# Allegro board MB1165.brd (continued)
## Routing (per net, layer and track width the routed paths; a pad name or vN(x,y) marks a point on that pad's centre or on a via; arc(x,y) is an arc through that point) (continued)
PWR_ENN: length 13.8
  TOP w0.127: U21.28 39.22,45.59 R147.2
  TOP w0.254: U18.3 R147.2
RESET#: length 385.7
  TOP w0.127: CN18.36 72.07,39.43 73.41,38.1 73.41,35.38 68.39,30.37 68.39,27.24 62.61,21.46 55.05,21.46 52.83,23.69 v1(52.83,24.13) 52.83,24.66 D16.2 ; U4.J1 77.54,142.96 77.54,144.21 v5(77.5,144.25) ; v1(133.88,120.47) 133.53,120.47 132.96,121.04 U6.29 ; R96.2 126.62,106.81 127.56,106.81 v1(128.27,107.51) ; B1.2 B1.3 53.78,10.99 C102.2 v1(53.72,12.19) ; U21.18 39.52,33.41 39.11,32.99 v1(37.97,32.99) ; v1(28.05,138.03) v1(33.43,138.03) D2.1 ; R114.2 20.71,100.2 21.59,99.33 21.59,98.81 v1(22.61,97.79)
  L3_SIG w0.102: v1(120.52,152.78) 119.68,153.62 111.28,153.62 110.97,153.92 91.59,153.92 87.91,150.24 83.69,150.24 82.04,148.59 82.04,147.57 80.39,145.92 80.39,144.91 79.45,143.97 77.78,143.97 v5(77.5,144.25) 77.39,144.35 77.39,146.41 76.09,147.71 73.65,147.71 69.52,151.84 66.6,151.84 64.54,153.9 43.79,153.9 43.43,153.54 v1(43.28,153.54) 43.15,153.42 40.64,153.42 39.93,152.7 38.28,152.7 33.22,147.65 33.22,142.95 33.58,142.6 33.58,138.18 v1(33.43,138.03) ; v1(23.14,113.26) 22.05,114.35 22.05,118.06 28.05,124.06 v1(28.05,138.03) ; v1(52.83,24.13) 52.83,26.44 51.33,27.94 44.96,27.94 39.9,32.99 v1(37.97,32.99) 37.49,32.99 33.4,37.08 33.4,43.69 31.5,45.59 31.5,61.85 30.86,62.48 30.86,69.11 28.07,71.91 28.07,86.11 27.33,86.84 27.33,93.07 v1(22.61,97.79)
  BOTTOM w0.127: v1(53.72,12.19) 51.18,14.73 51.18,22.48 v1(52.83,24.13) ; v1(22.61,97.79) 22.02,98.37 22.02,112.14 v1(23.14,113.26) ; R213.1 42.8,154.31 42.8,154.05 43.28,153.57 v1(43.28,153.54) ; v1(120.52,152.78) 128.65,144.65 128.65,129.39 132.36,125.68 132.36,121.77 133.65,120.47 v1(133.88,120.47) 132.74,119.33 132.74,110.36 129.89,107.51 v1(128.27,107.51)
STL_USB_DM: length 35.9
  TOP w0.155: R177.2 17.72,23.56 18.73,23.56 20.7,25.53 20.7,28.86 26.54,34.7 26.54,40.54 27.66,41.66 35.56,41.66 37.16,40.05 37.16,38.99 37.22,38.93 U21.32
STL_USB_DP: length 35.2
  TOP w0.155: R180.2 17.72,23.18 18.89,23.18 21.08,25.37 21.08,28.7 26.92,34.54 26.92,40.39 27.81,41.27 35.4,41.27 36.78,39.89 36.78,38.99 36.72,38.93 U21.33
STLINK_RX: length 47
  TOP w0.127: CN24.1 51.18,17.53 51.18,22.61 42.88,30.9 U21.13
  BOTTOM w0.127: CN24.1 49.02,13.34 51.44,10.92 56.01,10.92 67.06,21.97 JP19.3
STLINK_TX: length 48.9
  TOP w0.127: CN24.2 49.02,23.75 43.47,29.3 U21.12
  BOTTOM w0.127: CN24.2 50.16,16.76 50.16,13.34 52.07,11.43 55.5,11.43 65.66,21.59 65.66,26.54 JP15.3
STM_JTCK_SWCLK: length 6.3
  TOP w0.127: CN20.3 29.34,35.43 31.5,35.43 32.47,36.41 U21.37
STM_JTMS_SWDIO: length 9.9
  TOP w0.127: CN20.1 29.34,37.97 33.53,37.97 34.67,36.83 35.81,36.83 36.22,37.24 U21.34
STM_RST: length 6.4
  TOP w0.127: v1(39.12,31.62) 38.22,30.73 U21.7
  BOTTOM w0.127: R291.1 SB84.2 C181.2 v1(39.12,31.62)
T_JTDO: length 258.4
  TOP w0.127: R92.2 127.13,108.58 v1(127.38,108.33) ; v1(133.35,141.35) 133.35,138.3 136.14,135.51 145.29,135.51 146.43,134.37 146.43,130.43 148.08,128.78 150.14,128.78 151.26,127.67 151.26,126.24 151.69,125.81 v1(151.69,125.78) ; U21.16 41,32.41 40.87,32.54 37.69,32.54 36.96,33.27 36.96,35.18 v1(37.72,35.94) U21.31
  L3_SIG w0.102: JP5.1 99.52,132.41 112.85,132.41 113.39,131.88 119.68,131.88 127.89,140.08 132.08,140.08 v1(133.35,141.35) ; v1(151.69,125.78) 151.69,120.86 150.21,119.38 145.89,119.38 142.34,115.82 140.69,115.82 137,112.14 133.48,112.14 130.81,109.47 127.89,109.47 127.38,108.97 v1(127.38,108.33) 127.38,106.17 128.5,105.05 128.5,101.5 126.85,99.85 125.35,99.85 123.04,97.54 121.74,97.54 118.73,94.53 118.73,93.43 112.52,87.22 112.52,81.03 112.9,80.64 112.9,77.52 110.24,74.85 110.24,72.85 78.54,41.15 62.92,41.15 61.26,39.5 57.02,39.5 56.44,40.08 52.22,40.08 50.29,38.15 50.29,34.29 47.9,31.9 44.53,31.9 44.07,32.36 44.07,32.51 43.69,32.89 42.8,32.89 40.51,35.18 38.49,35.18 v1(37.72,35.94)
TOUCH_INT: length 92.9
  TOP w0.127: v1(58.01,40.39) U22.27 ; CN15.4 110.32,80.65 109.93,80.26 108.28,80.26 105.66,77.65 105.66,55.12 104.14,53.59 70.87,53.59 68.83,51.56 68.83,47.12 69.53,46.42 CN18.39 v1(69.53,42.61)
  L3_SIG w0.102: v1(69.53,42.61) 68.33,43.81 61.44,43.81 v1(58.01,40.39)
U5V_ST_LINK: length 36.3
  TOP w0.508: 35.83,58.04 C59.2 35.18,57.43 ; 36.22,57.53 U18.6 ; U18.7 34.95,57.02
  BOTTOM w1.016: 35.48,60.91 5.38,60.91 4.57,61.72 JP14.11
  vias: v1(36.2,60.07) v1(36.2,59.44)
ULPI_D1: length 76.3
  TOP w0.127: U8.23 31.73,107.29 33.78,109.35 36.5,109.35 37.13,108.71 v1(37.13,107.19)
  L3_SIG w0.102: v1(44.96,124.33) 47.75,124.33 47.88,124.21 47.88,123.83 47.75,123.7 42.8,123.7 42.67,123.57 42.67,123.32 42.8,123.19 44.2,123.19 44.32,123.06 44.32,122.81 44.2,122.68 42.8,122.68 42.67,122.56 42.67,122.35 42.8,122.22 43.7,122.22 43.81,122.11 43.81,121.94 43.7,121.82 42.77,121.82 42.67,121.72 42.67,121.51 42.77,121.41 43.59,121.41 43.69,121.31 43.69,121.11 43.59,121.01 42.77,121.01 42.67,120.9 42.67,116.46 42.55,116.33 41.02,116.33 40.89,116.21 40.89,116.03 41.02,115.91 43.18,115.91 43.28,115.81 43.28,115.61 43.18,115.5 41.05,115.5 40.92,115.38 40.92,115.22 41.05,115.1 43.18,115.1 43.28,115 43.28,114.79 43.18,114.69 41.05,114.69 40.92,114.56 40.92,114.41 41.05,114.29 43.18,114.29 43.28,114.18 43.28,113.98 43.18,113.88 41.05,113.88 40.92,113.75 40.92,113.6 41.05,113.47 43.18,113.47 43.28,113.37 43.28,113.17 43.18,113.07 41.05,113.07 40.92,112.94 40.92,112.71 41.02,112.61 42.82,112.61 42.93,112.51 42.93,112.09 42.66,111.82 42.51,111.82 42.1,112.24 41.95,112.24 41.81,112.09 41.81,111.95 42.23,111.53 42.23,111.39 42.08,111.25 41.94,111.25 41.52,111.66 41.38,111.66 41.24,111.52 41.24,111.37 41.65,110.96 41.65,110.81 41.51,110.67 41.36,110.67 40.95,111.09 40.8,111.09 40.66,110.94 40.66,110.8 41.08,110.38 41.08,110.24 40.93,110.1 40.79,110.1 40.37,110.51 40.23,110.51 40.09,110.37 40.09,110.22 40.5,109.81 40.5,109.66 40.36,109.52 40.21,109.52 39.8,109.94 39.65,109.94 39.51,109.79 39.51,109.65 39.92,109.23 39.92,109.09 39.78,108.95 39.64,108.95 39.22,109.36 39.08,109.36 38.93,109.22 38.93,109.07 39.35,108.66 39.35,108.51 39.21,108.37 39.06,108.37 38.65,108.79 38.5,108.79 38.36,108.64 38.36,108.5 38.77,108.08 38.77,107.94 38.63,107.8 38.49,107.8 38.07,108.21 37.93,108.21 37.78,108.07 37.78,107.48 37.49,107.19 v1(37.13,107.19)
  BOTTOM w0.127: SB79.1 v1(44.96,124.33)
ULPI_D2: length 85.3
  TOP w0.127: U8.22 31.99,106.8 33.91,108.71 v1(34.8,108.71)
  L3_SIG w0.102: v1(44.83,140.72) 47.98,140.72 48.11,140.84 48.11,141.07 47.98,141.2 38.63,141.2 38.51,141.07 38.51,140.84 38.63,140.72 42.67,140.72 42.8,140.59 42.8,140.41 42.67,140.29 38.65,140.29 38.53,140.17 38.53,140 38.65,139.88 42.68,139.88 42.8,139.76 42.8,139.59 42.68,139.47 38.63,139.47 38.51,139.35 38.51,139.19 38.63,139.07 42.91,139.07 43.03,138.95 43.03,138.78 42.91,138.66 38.63,138.66 38.51,138.53 38.51,132.36 37.97,131.83 37.97,125.5 38.51,124.97 38.51,115.15 38.4,115.04 37.67,115.04 37.57,114.94 37.57,114.74 37.67,114.64 38.4,114.64 38.51,114.54 38.51,114.33 38.4,114.23 37.36,114.23 37.24,114.11 37.24,113.94 37.36,113.82 38.4,113.82 38.51,113.72 38.51,113.52 38.4,113.42 37.38,113.42 37.26,113.3 37.26,113.13 37.38,113.01 38.4,113.01 38.51,112.91 38.51,112.42 v1(34.8,108.71)
  BOTTOM w0.127: SB50.1 45.34,141.22 v1(44.83,140.72)
ULPI_D5: length 70.6
  TOP w0.127: U8.19 32.5,105.29 33.27,104.52 v1(34.8,104.52)
  L3_SIG w0.102: v1(34.8,104.52) 35.66,104.52 35.79,104.65 35.79,107.47 39.98,111.66 39.98,117.31 40.18,117.51 41.28,117.51 41.4,117.63 41.4,117.8 41.28,117.92 40.03,117.92 39.93,118.02 39.93,118.22 40.03,118.32 41.55,118.32 41.66,118.42 41.66,118.63 41.55,118.73 40.03,118.73 39.93,118.83 39.93,119.03 40.03,119.14 41.55,119.14 41.66,119.24 41.66,119.44 41.55,119.54 40.03,119.54 39.93,119.64 39.93,119.85 40.03,119.95 41.55,119.95 41.66,120.05 41.66,120.25 41.55,120.36 40.03,120.36 39.93,120.46 39.93,120.66 40.03,120.76 41.55,120.76 41.66,120.86 41.66,121.07 41.55,121.17 40.03,121.17 39.93,121.27 39.93,121.47 40.03,121.57 41.55,121.57 41.66,121.68 41.66,121.88 41.55,121.98 40.03,121.98 39.93,122.08 39.93,122.29 40.03,122.39 41.55,122.39 41.66,122.49 41.66,122.69 41.55,122.79 40.03,122.79 39.93,122.9 39.93,123.1 40.03,123.2 41.55,123.2 41.66,123.3 41.66,123.5 41.55,123.61 40.03,123.61 39.93,123.71 39.93,123.91 40.03,124.01 41.55,124.01 41.66,124.11 41.66,124.32 41.55,124.42 40.03,124.42 39.93,124.52 39.93,124.72 40.03,124.83 41.55,124.83 41.66,124.93 41.66,125.13 41.55,125.23 40.03,125.23 39.93,125.33 39.93,125.7 40.06,125.83 42.19,125.83 42.32,125.96 42.32,126.24 42.19,126.36 40.06,126.36 39.93,126.49 39.93,126.72 40.06,126.85 40.69,126.85 40.82,126.97 40.82,128.64 40.69,128.76 39.84,128.76 v1(39.52,128.45)
  BOTTOM w0.127: SB74.1 39.85,128.91 39.52,128.57 v1(39.52,128.45)
ULPI_D7: length 61.8
  TOP w0.127: U8.17 v1(31.7,104.29)
  L3_SIG w0.102: v1(43.81,152.58) 41.45,152.58 39.62,150.75 39.24,150.75 35.05,146.56 35.05,145.11 34.42,144.48 34.42,125.6 36.45,123.57 36.45,116.13 35.05,114.73 35.05,113.03 31.7,109.68 v1(31.7,104.29)
  BOTTOM w0.127: SB29.1 46.86,153.16 45.47,153.16 44.88,152.58 v1(43.81,152.58)
USB_RENUMN: length 21.2
  TOP w0.127: U21.38 32.73,35.9 29.59,32.77 27.18,32.77 23.24,28.83 v1(23.24,21.84)
  BOTTOM w0.127: R293.2 v1(23.24,21.84)
VREF+: length 15.5
  TOP w0.381: v5(73.21,143.29) 73.61,142.89 U4.P1
  TOP w0.508: R33.2 v1(67.94,145.54)
  BOTTOM w0.381: v5(73.21,143.29) 73.21,143.31 73.66,143.76 C113.2
  BOTTOM w0.508: v5(73.21,143.29) 72.87,143.29 72.26,143.89 69.72,143.89 68.07,145.54 v1(67.94,145.54) 67.18,146.3 C108.1 66.55,148.72 TP6.1
VUSB_ST_LINK: length 83.8
  TOP w0.508: 34.47,50.59 U18.2 ; U18.2 34.95,49.5 ; U18.2 34.95,51.94 ; 31.75,49.33 C65.1 ; C65.1 32.72,50.16 ; C65.1 30.78,50.16 ; C65.1 31.75,51 ; 31.27,52.45 R144.1 ; R144.1 31.88,51.85 ; R144.1 32.49,52.45 ; R147.1 35.2,49.07 ; R147.1 35.2,48.11 ; R147.1 34.72,48.59 ; D11.1 27.43,76.96 ; D11.1 26.82,77.57 ; D11.1 26.82,76.35 ; D11.1 26.2,76.96 ; CN22.1 11.68,21.59 R187.1 ; 33.2,50.59 U18.1 ; U18.1 33.68,49.5 ; U18.1 34.16,50.59 ; U18.1 33.68,51.68
  L3_SIG w1.016: 18.97,22.43 26.37,29.82 26.37,42.52 28.83,44.98 v1(28.83,52.73) ; 26.29,75.69 26.29,73.28 25.4,72.39 25.4,63.88 28.83,60.45 v1(28.83,56.39)
  BOTTOM w0.508: 19.3,22.33 R292.2 18.71,21.72
  BOTTOM w1.016: 17.02,22.23 CN22.1
  vias: v1(17.98,22.33) v1(18.01,21.62) v1(18.57,22.63) v1(25.91,77.34) v1(25.91,76.58) v1(28.8,55.37) v1(28.8,54.66) v1(28.8,53.9)

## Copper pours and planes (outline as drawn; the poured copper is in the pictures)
+1V8 on TOP: 107.06,43.05 108.46,43.05 108.97,43.56 108.97,47.62 109.22,47.88 110.49,47.88 110.87,47.5 110.87,43.56 111.38,43.05 119.51,43.05 120.14,42.42 120.14,38.35 119.63,37.85 107.06,37.85 106.68,38.23 106.68,42.67
+1V8 on BOTTOM: 154.56,159.38 154.81,159.13 154.81,156.72 154.56,156.46 148.13,156.46 147.45,155.78 147.45,119.25 139.01,110.82 139.01,100.3 138.53,99.82 136.4,99.82 136.02,100.2 136.02,111.46 143.89,119.33 143.89,153.85 143.76,153.97 143.76,158.37 144.78,159.38
+1V8 on BOTTOM: 121.34,42.67 121.36,42.7 121.72,42.7 122.1,42.32 122.1,24.99 121.69,24.59 118.26,24.59 117.84,25.01 117.84,27.01 118.29,27.46 118.29,28.75 114.94,32.11 114.94,42.34 115.27,42.67
+1V8 on L3_SIG: 134.75,101.47 137.79,101.47 138.3,100.97 138.3,98.42 123.06,83.19 123.06,40.89 120.14,37.97 116.08,37.97 115.82,38.23 115.82,42.67 116.71,43.56 117.98,43.56 119.25,44.83 119.25,88.39 123.38,92.52 125.79,92.52
+2V8 on TOP: 140.08,156.59 140.46,156.21 140.46,151 140.21,150.75 131.06,150.75 130.43,151.38 130.43,155.32 131.83,156.72 131.83,160.53 131.95,160.66 133.6,160.66 133.73,160.53 133.73,157.23 134.37,156.59
+2V8 on L4_VCC: 136.76,137.16 134.87,139.04 134.87,156.1 137.27,158.5 156.34,158.5 156.34,148.34 156.34,148.33 156.34,146.18 156.21,146.05 153.03,146.05 152.15,145.16 152.15,137.77 151.53,137.16
+3V3 on TOP: 106.3,48.51 108.2,48.51 108.46,48.26 108.46,44.7 108.2,44.45 106.3,44.45 106.05,44.7 106.05,48.26
+3V3 on TOP: 43.31,56.13 60.33,56.13 60.71,55.75 60.71,52.32 60.2,51.82 56.26,51.82 55.75,51.31 55.75,44.2 55.24,43.69 43.56,43.69 42.55,44.7 42.55,55.37
+3V3 on L4_VCC: 0.51,0.51 0.51,13.93 19.56,13.93 20.19,14.57 20.19,15.62 20.45,15.88 30.32,15.88 31.33,16.89 31.33,26.01 31.97,26.65 40.54,26.65 42.5,28.61 42.5,40.06 41.02,41.54 26.76,41.54 24.07,44.24 24.07,69.76 22.46,71.36 0.51,71.36 0.51,82.03 2,82.03 2.39,82.43 2.39,83.5 2,83.9 0.51,83.9 0.51,86.78 2,86.78 2.39,87.18 2.39,88.25 2,88.65 0.51,88.65 0.51,96.39 2,96.39 2.39,96.78 2.39,97.86 2,98.25 0.51,98.25 0.51,101.14 2,101.14 2.39,101.53 2.39,102.61 2,103 0.51,103 0.51,106.93 5.95,106.93 6.6,107.59 6.6,111.1 5.95,111.76 3.41,111.76 3.3,111.87 3.3,113.69 3.41,113.79 5.19,113.79 6.35,114.96 6.35,116.1 6.96,116.71 7.34,116.71 8,117.37 8,118.85 7.6,119.25 0.51,119.25 0.51,172.21 156.34,172.21 156.34,159 137.05,159 134.37,156.32 134.37,138.83 136.55,136.65 151.74,136.65 152.65,137.56 152.65,144.91 153.29,145.54 155.96,145.54 156.34,145.16 156.34,52.91 155.69,47.08 156.34,41.24 156.34,0.51 ; 1 cut-out
+3V3_ST_LINK on L4_VCC: 0.51,14.44 0.51,70.86 22.25,70.86 23.56,69.55 23.56,44.03 26.55,41.03 40.81,41.03 42,39.85 42,28.82 40.33,27.16 31.76,27.16 30.83,26.22 30.83,17.27 30.06,16.51 20.19,16.51 19.56,15.88 19.56,14.82 19.18,14.44
+5V on TOP: 130.68,157.48 128.78,157.48 128.27,157.99 128.27,162.23 128.47,162.43 130.86,162.43 131.06,162.23 131.06,157.86
+5V on TOP: 6.02,76.35 6.54,76.87 13.32,76.87 13.77,76.43 13.77,71.04 13.83,70.98 13.83,68.47 15.75,66.55 44.89,66.55 46.61,68.26 48.2,68.26 48.64,67.82 48.64,62.61 47.88,61.85 47.88,56.9 47.62,56.64 43.81,56.64 43.43,57.02 43.43,59.69 41.91,61.21 6.65,61.21 6.02,61.85
+5V on BOTTOM: 13.84,92.15 12.09,92.15 11.68,92.56 11.68,97.97 16.59,102.87 16.59,115.16 17.22,115.8 21.01,115.8 21.21,115.6 21.21,114.17 19.91,112.88 19.91,102.57 14.05,96.7 14.05,92.35
+5V on L3_SIG: 8.66,97.46 13.21,97.46 13.74,96.93 13.74,72.75 12.62,71.63 6.38,71.63 6.05,71.96 6.05,76.63 10.64,81.23 10.64,94.36 10.19,94.82 8.81,94.82 8.51,95.12 8.51,97.31
+5V on L3_SIG: 130.07,161.59 128.57,161.59 128.32,161.85 128.32,167.94 125.93,170.33 115.44,170.33 110.39,165.28 109.65,165.28 107.92,167 71.27,167 69.9,168.38 30.23,168.38 28.92,167.07 28.92,156.53 28.57,156.18 28.57,149.61 19.3,140.34 19.3,118.24 20.93,116.61 20.95,116.61 21.36,116.2 21.36,113.51 21.03,113.18 17.5,113.18 12.19,118.49 12.19,142.56 25.34,155.7 25.34,168.16 28.42,171.25 113.42,171.25 114.16,171.98 127.91,171.98 130.33,169.57 130.33,161.85
D5V on TOP: 42.93,125.91 44.22,125.91 44.58,125.55 44.58,121.62 45.06,121.13 45.06,120.7 44.88,120.52 43.97,120.52 43.64,120.85 43.64,122.58 43.66,122.61 43.66,124.69 43.31,125.04 43.03,125.04 42.93,125.15
D5V on TOP: 39.67,125.68 39.67,123.88 37.21,121.41 26.59,121.41 26.42,121.59 26.42,122.56 26.67,122.81 36.07,122.81 39.12,125.86 39.5,125.86
D5V on TOP: 106.93,125.98 108.28,125.98 108.38,125.88 108.38,124.97 108.25,124.84 106.93,124.84 106.81,124.97 106.81,125.86
D5V on BOTTOM: 14.68,95.22 15.21,95.22 21.54,101.55 21.54,112.12 22.89,113.46 22.89,116.71 27.61,121.44 28.07,121.44 28.27,121.64 28.27,122.66 28.09,122.83 26.82,122.83 21.84,117.86 21.84,113.92 20.42,112.5 20.42,102.06 14.43,96.06 14.43,95.48
D5V on L3_SIG: 107.19,125.98 108.33,125.98 108.58,125.73 108.58,124.59 105.92,121.92 98.73,121.92 96.57,119.76 62.36,119.76 60.55,121.56 47.88,121.56 46.58,120.27 44.07,120.27 43.94,120.4 43.94,121.54 44.2,121.79 45.82,121.79 46.58,122.56 61.21,122.56 62.74,121.03 96.06,121.03 98.09,123.06 104.9,123.06 106.81,124.97 106.81,125.6
D5V on L3_SIG: 14.71,96.47 15.6,96.47 15.75,96.32 15.75,77.22 15.49,76.96 15.49,73.91 15.75,73.66 15.75,71.93 10.36,66.55 3.84,66.55 3.4,66.98 3.4,68.99 3.73,69.32 8.36,69.32 8.56,69.11 10.97,69.11 14.22,72.36 14.22,95.99
GND on BOTTOM (solid shape): 37.59,29.56 38.1,30.06 38.1,28.7 37.08,28.7 37.08,30.07
GND on TOP: 111.89,48.51 118.75,48.51 119,48.26 119,44.32 118.62,43.94 111.89,43.94 111.63,44.2 111.63,48.26
GND on TOP: 22.23,60.33 27,60.33 27.46,59.87 27.46,55.24 26.82,54.61 22.1,54.61 21.72,54.99 21.72,59.82
GND on TOP: 141.48,156.34 143.64,156.34 144.15,155.83 144.15,151.38 143.64,150.88 141.22,150.88 140.97,151.13 140.97,155.83
GND on TOP: 54.48,56.9 54.23,56.64 50.55,56.64 50.36,56.83 50.36,61.28 50.16,61.47 50.16,66.59 51.14,67.56 59.5,67.56 61.59,65.47 61.59,57.15 61.34,56.9
GND on TOP: 77.6,151.38 69.47,151.38 69.22,151.64 69.22,155.45 71.75,157.99 91.57,157.99 91.95,157.61 91.95,150.75 91.03,149.83 87.02,149.83 85.72,151.13 77.85,151.13
GND on TOP: 27.69,19.05 26.67,20.07 26.67,31.37 27.56,32.26 30.21,32.26 30.34,32.13 30.34,30.75 32.4,28.68 32.4,26.82 33.13,26.09 43.94,26.09 45.21,24.82 45.21,20.4 43.87,19.05
GND on TOP: 22.86,117.86 34.67,117.86 34.92,117.6 34.92,113.41 32.89,111.38 30.48,111.38 30.48,112.78 26.8,112.78 26.8,111.38 25.53,111.38 25.34,111.19 25.34,109.41 25.15,109.22 22.35,109.22 21.97,109.6 21.97,116.97
GND on TOP: 144.17,132.08 144.53,131.72 144.53,117.35 144.27,117.09 137.79,117.09 137.29,117.6 137.29,131.32 138.05,132.08
GND on BOTTOM: 70.82,156.64 80.01,156.64 80.7,155.96 80.7,152.4 79.55,151.26 71.04,151.26 69.14,153.16 69.14,154.97
GND on BOTTOM: 31.47,25.98 44.15,25.98 45.11,25.02 45.11,19.86 44.48,19.23 31.24,19.23 30.78,19.68 30.78,25.3
GND on BOTTOM: 24.92,117.91 32.44,117.91 33.63,116.71 33.63,112.55 32.64,111.56 24.43,111.56 24.42,111.57 24.23,111.57 23.94,111.86 22.66,111.86 22.56,111.96 22.56,112.34 23.22,113 23.22,116.2
GND on L2_GND, L5_GND: 0.51,0.51 0.51,82.03 2,82.03 2.39,82.43 2.39,83.5 2,83.9 0.51,83.9 0.51,86.78 2,86.78 2.39,87.18 2.39,88.25 2,88.65 0.51,88.65 0.51,96.39 2,96.39 2.39,96.78 2.39,97.86 2,98.25 0.51,98.25 0.51,101.14 2,101.14 2.39,101.53 2.39,102.61 2,103 0.51,103 0.51,106.93 5.95,106.93 6.6,107.59 6.6,111.1 5.95,111.76 3.41,111.76 3.3,111.87 3.3,113.69 3.41,113.79 5.19,113.79 6.35,114.96 6.35,116.1 6.96,116.71 7.34,116.71 8,117.37 8,118.85 7.6,119.25 0.51,119.25 0.51,172.21 156.34,172.21 156.34,52.91 155.69,47.08 156.34,41.24 156.34,0.51
GND on L3_SIG: outline of 152 points within 0.56,0.64 156.34,119.63
GND on L3_SIG: 41.15,106.3 48.39,106.3 49.91,104.78 49.91,79.5 66.42,62.99 90.55,62.99 92.84,65.28 93.47,65.28 93.6,65.15 93.6,60.58 81.53,48.51 69.47,48.51 68.2,47.24 59.44,47.24 58.93,46.74 58.93,45.34 54.99,41.4 51.69,41.4 48.11,37.82 35.81,37.82 35.18,38.46 35.18,45.47 34.54,46.1 34.54,61.59 33.02,63.12 33.02,70.36 29.84,73.53 29.84,93.55 39.5,103.2 39.5,104.65
GND on L3_SIG: 24.23,118.49 33.22,118.49 33.99,117.73 33.99,113.11 30.81,109.93 30.81,103.58 30.1,102.87 24.21,102.87 23.75,103.33 23.75,106.81 22.1,108.46 22.1,112.09 22.83,112.83 22.83,117.09
VBUS_FS2 on TOP (solid shape): 15.24,113.54 14.22,113.54 14.22,114.9 14.73,114.39 15.24,114.9
VDD_MCU on BOTTOM: 59.56,149.86 60.58,150.88 61.85,150.88 62.36,150.37 62.36,139.06 62.1,138.81 59.82,138.81 59.56,139.06
VDD_MCU on L4_VCC: 58.78,130.3 58.17,130.92 58.17,150.52 58.78,151.13 61.87,151.13 62.23,150.77 62.23,148.23 62.89,147.57 71.73,147.57 74.27,150.11 87.78,150.11 89.41,148.48 89.41,131.93 87.78,130.3
DSI_VDD12 on BOTTOM: 77.7,132.77 78.03,132.44 78.03,132.23 77.98,132.18 77.17,132.18 76.34,133.01 76.34,134.79 76.48,134.92 77.6,134.92 77.7,134.82
E5V on TOP: 20.83,55.12 20.83,59.82 20.32,60.33 6.1,60.33 5.72,60.71 5.72,65.79 5.21,66.29 1.27,66.29 1.02,66.04 1.02,54.74 1.4,54.36 10.92,54.36 11.3,54.74 20.45,54.74
LCD_BL_CTRL on BOTTOM (solid shape): 116.59,123.44 115.22,123.44 115.73,123.95 115.22,124.46 116.59,124.46
LCD_G0 on BOTTOM (solid shape): 46.45,139.7 46.95,139.19 45.59,139.19 45.59,140.21 46.96,140.21
LCD_G1 on BOTTOM (solid shape): 46.45,125.85 46.95,125.35 45.59,125.35 45.59,126.36 46.96,126.36
LCD_G5 on BOTTOM (solid shape): 38.39,137.41 37.88,136.91 36.96,136.91 36.96,137.92 37.88,137.92
LCD_G6 on BOTTOM (solid shape): 41.43,153.67 40.93,153.16 40.01,153.16 40.01,154.18 40.93,154.18
LCD_G7 on BOTTOM (solid shape): 48.13,155.19 46.77,155.19 47.28,155.7 46.77,156.21 48.13,156.21
LCD_R0 on TOP (solid shape): 95.5,141.5 94.58,141.5 94.08,142.01 94.58,142.52 95.5,142.52
MIC_CLK on BOTTOM (solid shape): 120.65,15.53 120.14,16.04 119.63,15.53 119.63,16.89 120.65,16.89
MIC_DATA on BOTTOM (solid shape): 129.92,16.1 129.41,15.59 128.91,16.1 128.91,17.02 129.92,17.02
MII_TXD0 on BOTTOM (solid shape): 96.16,155.65 94.8,155.65 95.31,156.16 94.8,156.67 96.16,156.67
NETC5_1 on TOP: 134.49,163.32 136.53,163.32 137.03,162.81 137.03,159.64 137.16,159.51 139.19,159.51 139.45,159.26 139.45,157.35 139.19,157.1 134.87,157.1 134.24,157.73 134.24,163.07
NETC6_2 on TOP (solid shape): 64.64,159.99 64.14,159.48 63.63,159.99 63.63,160.91 64.64,160.91
NETC6_2 on BOTTOM (solid shape): 40.86,144.4 41.37,143.89 40.01,143.89 40.01,144.91 41.37,144.91
NETC7_2 on TOP (solid shape): 70.99,160.12 70.48,159.61 69.98,160.12 69.98,161.04 70.99,161.04
NETC7_2 on BOTTOM (solid shape): 116.59,132.72 115.22,132.72 115.73,133.23 115.22,133.73 116.59,133.73
NETC8_2 on BOTTOM (solid shape): 48.13,150.24 46.77,150.24 47.28,150.75 46.77,151.26 48.13,151.26
NETC9_2 on BOTTOM (solid shape): 40.86,147.52 41.37,147.02 40.01,147.02 40.01,148.03 41.37,148.03
NETC10_2 on BOTTOM (solid shape): 109.57,130.81 110.07,130.3 108.71,130.3 108.71,131.32 110.08,131.32
NETC11_1 on BOTTOM (solid shape): 48.13,130.05 47.21,130.05 46.7,130.56 47.21,131.06 48.13,131.06
NETC12_2 on BOTTOM (solid shape): 48.13,136.14 47.21,136.14 46.7,136.65 47.21,137.16 48.13,137.16
NETC13_2 on BOTTOM (solid shape): 42.67,140.84 41.75,140.84 41.24,141.35 41.75,141.86 42.67,141.86
NETC14_2 on BOTTOM (solid shape): 48.13,147.07 47.21,147.07 46.7,147.57 47.21,148.08 48.13,148.08
NETC15_1 on BOTTOM (solid shape): 41.56,139.06 41.05,138.56 40.13,138.56 40.13,139.57 41.05,139.57
NETC17_1 on TOP (solid shape): 64.64,158.37 63.63,158.37 63.63,159.73 64.13,159.22 64.64,159.73
NETC18_2 on TOP (solid shape): 70.99,158.5 69.98,158.5 69.98,159.86 70.48,159.35 70.99,159.86
NETC18_2 on BOTTOM (solid shape): 116.59,126.49 115.22,126.49 115.73,127 115.22,127.51 116.59,127.51
NETC35_1 on TOP: 0.89,107.57 0.51,107.95 0.51,109.6 0.64,109.73 2.03,109.73 2.41,110.11 2.41,111.51 2.16,111.76 0.76,111.76 0.53,111.99 0.53,114.5 0.58,114.55 0.64,114.55 0.68,114.6 2,114.6 2.39,115 2.39,116.07 2,116.47 0.76,116.47 0.64,116.59 0.64,118.75 5.72,118.75 5.84,118.87 7.24,118.87 7.49,118.62 7.49,117.6 7.11,117.22 6.73,117.22 5.84,116.33 5.84,114.94 5.08,114.17 3.3,114.17 3.05,113.92 3.05,111.76 3.43,111.38 5.59,111.38 6.22,110.74 6.22,107.82 5.97,107.57
NETC35_1 on L2_GND, L4_VCC, L5_GND: 0.51,107.44 0.51,109.85 2,109.85 2.39,110.25 2.39,111.32 2,111.72 0.51,111.72 0.51,114.6 2,114.6 2.39,115 2.39,116.07 2,116.47 0.51,116.47 0.51,118.75 7.39,118.75 7.49,118.64 7.49,117.58 7.13,117.22 6.75,117.22 5.84,116.31 5.84,115.17 4.97,114.3 3.2,114.3 2.79,113.9 2.79,111.65 3.2,111.25 5.74,111.25 6.1,110.89 6.1,107.8 5.74,107.44
NETC37_1 on TOP (solid shape): 15.24,115.16 14.73,114.65 14.22,115.16 14.22,116.08 15.24,116.08
NETC37_1 on TOP (solid shape): 11.94,114.72 11.43,115.22 10.92,114.71 10.92,116.08 11.94,116.08
NETC63_1 on TOP: 65.15,52.76 66.93,52.76 67.06,52.63 67.06,47.42 66.17,46.53 65.41,46.53 64.9,47.04 64.9,52.5
NETC63_2 on TOP: 61.98,52.76 63.88,52.76 64.26,52.38 64.26,46.92 64.68,46.5 64.68,46.11 64.77,46.03 64.77,43.36 64.52,43.11 62.1,43.11 61.59,43.61 61.59,52.38
NETC64_1 on TOP: 24.89,46.86 24.51,46.48 21.97,46.48 21.72,46.74 21.72,53.72 21.84,53.85 24.77,53.85 24.89,53.72
NETC64_2 on TOP: 9.65,33.15 3.18,33.15 2.29,34.04 2.29,43.94 7.37,49.02 7.37,49.91 9.02,51.56 12.45,51.56 13.72,52.83 20.45,52.83 21.21,52.07 21.21,46.86 20.83,46.48 12.45,46.48 8.38,42.42 8.38,37.08 10.03,35.43 10.03,33.53
NETC142_2 on L3_SIG: 131.19,126.36 131.57,125.98 131.57,116.46 130.94,115.82 127.25,115.82 127,116.08 127,125.98 127.38,126.36
NETCN1_3 on BOTTOM (solid shape): 116.59,121.92 115.67,121.92 115.16,122.43 115.67,122.94 116.59,122.94
NETCN1_5 on BOTTOM (solid shape): 48.13,145.54 46.77,145.54 47.28,146.05 46.77,146.56 48.13,146.56
NETCN1_9 on BOTTOM (solid shape): 42.55,133.35 41.18,133.35 41.69,133.86 41.18,134.37 42.55,134.37
NETCN1_11 on BOTTOM (solid shape): 111.25,124.97 110.33,124.97 109.82,125.48 110.33,125.98 111.25,125.98
NETCN1_13 on BOTTOM (solid shape): 42.55,135.25 41.18,135.25 41.69,135.77 41.18,136.27 42.55,136.27
NETCN1_21 on BOTTOM (solid shape): 110.14,135.76 109.63,135.25 108.71,135.25 108.71,136.27 109.63,136.27
NETCN1_23 on BOTTOM (solid shape): 110.14,137.29 109.63,136.78 108.71,136.78 108.71,137.79 109.63,137.79
NETCN4_31 on BOTTOM (solid shape): 48.13,142.49 46.77,142.49 47.28,143 46.77,143.51 48.13,143.51
NETCN5_3 on BOTTOM (solid shape): 77.47,149.83 76.96,149.32 76.45,149.83 76.45,150.75 77.47,150.75
NETCN5_6 on BOTTOM (solid shape): 74.3,149.83 73.79,149.32 73.28,149.83 73.28,150.75 74.3,150.75
NETCN6_3 on BOTTOM (solid shape): 80.77,149.83 80.26,149.32 79.76,149.83 79.76,150.75 80.77,150.75
NETCN6_4 on BOTTOM (solid shape): 84.45,149.83 83.95,149.32 83.44,149.83 83.44,150.75 84.45,150.75
NETCN12_12 on TOP (solid shape): 95.5,138.2 94.14,138.2 94.65,138.71 94.14,139.22 95.5,139.22
NETCN12_14 on TOP (solid shape): 95.5,139.85 94.14,139.85 94.65,140.36 94.14,140.87 95.5,140.87
NETCN12_16 on TOP (solid shape): 95.5,144.7 94.14,144.7 94.65,145.21 94.14,145.72 95.5,145.72
NETCN12_18 on TOP (solid shape): 90.17,148.5 89.66,149 89.15,148.49 89.15,149.86 90.17,149.86
NETCN12_20 on TOP (solid shape): 128.52,99.57 127.51,99.57 127.51,100.93 128.01,100.42 128.52,100.93
NETCN14_4 on BOTTOM (solid shape): 40.99,130.43 41.49,129.92 40.13,129.92 40.13,130.94 41.5,130.94
NETCN17_3 on BOTTOM (solid shape): 109.57,119.63 110.07,119.13 108.71,119.13 108.71,120.14 110.08,120.14
NETCN17_7 on BOTTOM (solid shape): 111.25,123.44 110.33,123.44 109.82,123.95 110.33,124.46 111.25,124.46
NETCN19_1 on TOP: 12.83,37.47 12.07,36.7 9.78,36.7 9.02,37.47 9.02,41.91 12.95,45.85 23.11,45.85 23.37,45.59 23.37,43.69 22.73,43.05 15.75,43.05 12.83,40.13
NETD5_C3 on BOTTOM (solid shape): 116.59,129.67 115.22,129.67 115.73,130.18 115.22,130.68 116.59,130.68
NETD6_C3 on BOTTOM (solid shape): 37.81,135.76 38.32,135.25 36.96,135.25 36.96,136.27 38.32,136.27
NETD6_D3 on BOTTOM (solid shape): 37.81,133.86 38.32,133.35 36.96,133.35 36.96,134.37 38.32,134.37
NETJP7_3 on BOTTOM (solid shape): 116.59,124.97 115.22,124.97 115.73,125.48 115.22,125.98 116.59,125.98
NETJP19_2 on BOTTOM (solid shape): 109.57,129.28 110.07,128.78 108.71,128.78 108.71,129.79 110.08,129.79
NETL2_1 on TOP (solid shape): 11.94,114.46 11.94,113.54 10.92,113.54 10.92,114.46 11.43,114.97
NETLD8_2 on TOP: 11.3,93.98 12.07,93.98 12.19,93.85 12.19,91.95 11.94,91.69 11.94,89.41 11.68,89.15 8.64,89.15 8.38,89.41 8.38,91.82 9.02,92.46 11.05,92.46 11.18,92.58 11.18,93.85
NETR32_1 on TOP (solid shape): 90.17,148.24 90.17,147.32 89.15,147.32 89.15,148.24 89.66,148.75
NETR32_1 on TOP (solid shape): 91.69,148.24 91.69,147.32 90.68,147.32 90.68,148.24 91.19,148.75
NETR32_1 on TOP (solid shape): 93.22,148.24 93.22,147.32 92.2,147.32 92.2,148.24 92.71,148.75
NETR34_1 on TOP (solid shape): 128.52,101.19 128.02,100.68 127.51,101.19 127.51,102.11 128.52,102.11
NETR34_1 on TOP (solid shape): 130.05,103.54 130.05,102.62 129.03,102.62 129.03,103.54 129.54,104.04
NETR34_1 on TOP (solid shape): 130.05,101.19 129.54,100.68 129.03,101.19 129.03,102.11 130.05,102.11
NETR35_1 on TOP (solid shape): 94.39,145.21 93.88,144.7 92.96,144.7 92.96,145.72 93.88,145.72
NETR35_1 on TOP (solid shape): 94.42,143.69 93.91,143.18 92.99,143.18 92.99,144.2 93.91,144.2
NETR37_1 on TOP (solid shape): 90.46,140.72 89.95,140.21 89.03,140.21 89.03,141.22 89.95,141.22
NETR37_1 on TOP (solid shape): 94.39,140.36 93.88,139.85 92.96,139.85 92.96,140.87 93.88,140.87
NETR38_1 on TOP (solid shape): 94.39,138.71 93.88,138.2 92.96,138.2 92.96,139.22 93.88,139.22
NETR43_2 on BOTTOM (solid shape): 116.84,136.93 115.92,136.93 115.41,137.44 115.92,137.95 116.84,137.95
NETR44_2 on BOTTOM (solid shape): 48.13,128.52 47.21,128.52 46.7,129.03 47.21,129.54 48.13,129.54
NETR45_2 on BOTTOM (solid shape): 38.39,139.06 37.88,138.56 36.96,138.56 36.96,139.57 37.88,139.57
NETR46_2 on BOTTOM (solid shape): 48.13,144.02 46.77,144.02 47.28,144.53 46.77,145.03 48.13,145.03
NETR47_2 on BOTTOM (solid shape): 48.13,148.72 46.77,148.72 47.28,149.23 46.77,149.73 48.13,149.73
NETR57_2 on BOTTOM (solid shape): 48.13,137.67 47.21,137.67 46.7,138.18 47.21,138.68 48.13,138.68
NETR69_1 on BOTTOM (solid shape): 40.86,149.07 41.37,148.56 40.01,148.56 40.01,149.58 41.37,149.58
NETR88_2 on TOP (solid shape): 18.16,109.95 17.65,109.44 17.14,109.95 17.14,110.87 18.16,110.87
NETR88_2 on TOP (solid shape): 21.08,109.95 20.57,109.44 20.07,109.95 20.07,110.87 21.08,110.87
NETR116_2 on TOP: 10.92,97.79 13.84,97.79 13.97,97.66 13.97,94.74 13.84,94.61 10.92,94.61 10.67,94.87 10.67,97.54
NETR163_2 on BOTTOM (solid shape): 40.86,145.92 41.37,145.41 40.01,145.41 40.01,146.43 41.37,146.43
NETR243_2 on BOTTOM (solid shape): 65.15,135 63.79,135 64.3,135.51 63.79,136.02 65.15,136.02
NETR244_2 on TOP (solid shape): 89.88,135.26 90.39,134.75 89.03,134.75 89.03,135.76 90.39,135.76
NETR254_1 on BOTTOM (solid shape): 95.05,156.16 94.55,155.65 93.62,155.65 93.62,156.67 94.55,156.67
NETSB5_1 on TOP (solid shape): 93.22,148.5 92.71,149 92.2,148.49 92.2,149.86 93.22,149.86
NETSB7_1 on TOP (solid shape): 95.53,143.18 94.17,143.18 94.67,143.69 94.16,144.2 95.53,144.2
NETSB9_1 on TOP (solid shape): 91.57,140.21 90.21,140.21 90.71,140.71 90.2,141.22 91.57,141.22
NETSB12_2 on TOP (solid shape): 91.57,134.75 90.65,134.75 90.14,135.25 90.65,135.76 91.57,135.76
NETSB15_1 on TOP (solid shape): 18.16,108.33 17.14,108.33 17.14,109.69 17.65,109.19 18.16,109.7
NETSB16_1 on TOP (solid shape): 21.08,108.33 20.07,108.33 20.07,109.69 20.57,109.19 21.08,109.7
NETSB19_1 on TOP (solid shape): 130.05,99.57 129.03,99.57 129.03,100.93 129.54,100.42 130.05,100.93
NETSB25_2 on BOTTOM (solid shape): 120.65,15.27 120.65,14.35 119.63,14.35 119.63,15.27 120.14,15.78
NETSB26_1 on BOTTOM (solid shape): 129.42,15.33 129.92,15.84 129.92,14.48 128.91,14.48 128.91,15.84
NETSB31_2 on BOTTOM (solid shape): 48.13,151.76 47.21,151.76 46.7,152.27 47.21,152.78 48.13,152.78
NETSB32_2 on BOTTOM (solid shape): 41.43,152.15 40.93,151.64 40.01,151.64 40.01,152.65 40.93,152.65
NETSB34_2 on BOTTOM (solid shape): 41.43,150.62 40.93,150.11 40.01,150.11 40.01,151.13 40.93,151.13
NETSB48_1 on BOTTOM (solid shape): 40.86,142.87 41.37,142.37 40.01,142.37 40.01,143.38 41.37,143.38
NETSB56_2 on BOTTOM (solid shape): 42.67,136.91 41.75,136.91 41.24,137.41 41.75,137.92 42.67,137.92
NETSB63_2 on BOTTOM (solid shape): 64.04,135.51 63.53,135 62.61,135 62.61,136.02 63.53,136.02
NETSB67_1 on BOTTOM (solid shape): 116.59,131.19 115.22,131.19 115.73,131.7 115.22,132.21 116.59,132.21
PA0 on BOTTOM (solid shape): 42.55,145.41 41.62,145.41 41.12,145.92 41.62,146.43 42.55,146.43
PA0 on BOTTOM (solid shape): 42.55,143.89 41.62,143.89 41.12,144.4 41.62,144.91 42.55,144.91
PA0 on BOTTOM (solid shape): 42.55,142.37 41.62,142.37 41.12,142.88 41.62,143.38 42.55,143.38
PA1 on BOTTOM (solid shape): 47.02,150.75 46.51,150.24 45.59,150.24 45.59,151.26 46.51,151.26
PA1 on BOTTOM (solid shape): 47.02,149.22 46.51,148.72 45.59,148.72 45.59,149.73 46.51,149.73
PA2 on BOTTOM (solid shape): 42.55,148.56 41.62,148.56 41.12,149.07 41.62,149.58 42.55,149.58
PA2 on BOTTOM (solid shape): 42.55,147.04 41.62,147.04 41.12,147.55 41.62,148.06 42.55,148.06
PA4 on BOTTOM (solid shape): 47.02,143 46.51,142.49 45.59,142.49 45.59,143.51 46.51,143.51
PA7 on BOTTOM (solid shape): 47.02,146.05 46.51,145.54 45.59,145.54 45.59,146.56 46.51,146.56
PA7 on BOTTOM (solid shape): 47.02,144.53 46.51,144.02 45.59,144.02 45.59,145.03 46.51,145.03
PA8 on BOTTOM (solid shape): 115.47,127 114.97,126.49 114.05,126.49 114.05,127.51 114.97,127.51
PA8 on BOTTOM (solid shape): 115.47,125.48 114.97,124.97 114.05,124.97 114.05,125.98 114.97,125.98
PA8 on BOTTOM (solid shape): 115.47,123.95 114.97,123.44 114.05,123.44 114.05,124.46 114.97,124.46
PA9 on BOTTOM (solid shape): 111.25,128.78 110.33,128.78 109.82,129.29 110.33,129.79 111.25,129.79
PA11 on BOTTOM (solid shape): 111.25,130.3 110.33,130.3 109.82,130.81 110.33,131.32 111.25,131.32
PA12 on BOTTOM (solid shape): 115.47,133.22 114.97,132.72 114.05,132.72 114.05,133.73 114.97,133.73
PA12 on BOTTOM (solid shape): 115.47,131.7 114.97,131.19 114.05,131.19 114.05,132.21 114.97,132.21
PA12 on BOTTOM (solid shape): 115.47,130.18 114.97,129.67 114.05,129.67 114.05,130.68 114.97,130.68
PAR_D0 on BOTTOM (solid shape): 114.9,122.43 115.41,121.92 114.05,121.92 114.05,122.94 115.41,122.94
PAR_D2 on BOTTOM (solid shape): 109.57,125.47 110.07,124.97 108.71,124.97 108.71,125.98 110.08,125.98
PAR_D2 on BOTTOM (solid shape): 109.57,123.95 110.07,123.44 108.71,123.44 108.71,124.46 110.08,124.46
PAR_D6 on TOP (solid shape): 91.69,148.5 91.19,149 90.68,148.49 90.68,149.86 91.69,149.86
PAR_D7 on TOP (solid shape): 130.05,103.79 129.54,104.3 129.03,103.79 129.03,105.16 130.05,105.16
PAR_D11 on BOTTOM (solid shape): 111.25,119.13 110.33,119.13 109.82,119.63 110.33,120.14 111.25,120.14
PB0 on BOTTOM (solid shape): 48.13,125.35 47.21,125.35 46.7,125.86 47.21,126.36 48.13,126.36
PB0 on BOTTOM (solid shape): 48.13,123.83 47.21,123.83 46.7,124.33 47.21,124.84 48.13,124.84
PB1 on BOTTOM (solid shape): 48.13,140.72 47.21,140.72 46.7,141.22 47.21,141.73 48.13,141.73
PB1 on BOTTOM (solid shape): 48.13,139.19 47.21,139.19 46.7,139.7 47.21,140.21 48.13,140.21
PB5 on BOTTOM (solid shape): 47.02,155.7 46.51,155.19 45.59,155.19 45.59,156.21 46.51,156.21
PB5 on BOTTOM (solid shape): 47.02,153.92 46.51,153.42 45.59,153.42 45.59,154.43 46.51,154.43
PB12 on BOTTOM (solid shape): 42.67,129.92 41.75,129.92 41.24,130.43 41.75,130.94 42.67,130.94
PB12 on BOTTOM (solid shape): 42.67,128.4 41.75,128.4 41.24,128.91 41.75,129.41 42.67,129.41
PB14 on BOTTOM (solid shape): 39.5,133.35 38.58,133.35 38.07,133.86 38.58,134.37 39.5,134.37
PB14 on BOTTOM (solid shape): 41.43,133.86 40.93,133.35 40.01,133.35 40.01,134.37 40.93,134.37
PB15 on BOTTOM (solid shape): 39.5,135.25 38.58,135.25 38.07,135.76 38.58,136.27 39.5,136.27
PB15 on BOTTOM (solid shape): 41.43,135.76 40.93,135.25 40.01,135.25 40.01,136.27 40.93,136.27
PC0 on BOTTOM (solid shape): 42.55,150.11 41.18,150.11 41.69,150.62 41.18,151.13 42.55,151.13
PC1 on BOTTOM (solid shape): 46.45,152.27 46.95,151.76 45.59,151.76 45.59,152.78 46.96,152.78
PC1 on BOTTOM (solid shape): 46.45,147.57 46.95,147.07 45.59,147.07 45.59,148.08 46.96,148.08
PC2 on BOTTOM (solid shape): 40.99,141.35 41.49,140.84 40.13,140.84 40.13,141.86 41.5,141.86
PC3 on BOTTOM (solid shape): 46.45,138.17 46.95,137.67 45.59,137.67 45.59,138.68 46.96,138.68
PC3 on BOTTOM (solid shape): 46.45,136.65 46.95,136.14 45.59,136.14 45.59,137.16 46.96,137.16
PC4 on BOTTOM (solid shape): 39.5,138.56 38.13,138.56 38.64,139.07 38.14,139.57 39.5,139.57
PC4 on BOTTOM (solid shape): 42.67,138.56 41.31,138.56 41.82,139.07 41.31,139.57 42.67,139.57
PC5 on BOTTOM (solid shape): 46.45,130.55 46.95,130.05 45.59,130.05 45.59,131.06 46.96,131.06
PC5 on BOTTOM (solid shape): 46.45,129.03 46.95,128.52 45.59,128.52 45.59,129.54 46.96,129.54
PC14 on BOTTOM (solid shape): 83.95,149.06 84.45,149.57 84.45,148.21 83.44,148.21 83.44,149.57
PC15 on BOTTOM (solid shape): 80.27,149.06 80.77,149.57 80.77,148.21 79.76,148.21 79.76,149.57
PG11 on BOTTOM (solid shape): 111.25,135.25 109.89,135.25 110.4,135.77 109.89,136.27 111.25,136.27
PG13 on TOP (solid shape): 93.82,142.01 94.33,141.5 92.96,141.5 92.96,142.52 94.33,142.52
PH0 on BOTTOM (solid shape): 76.96,149.06 77.47,149.57 77.47,148.21 76.45,148.21 76.45,149.57
PH1 on BOTTOM (solid shape): 73.79,149.06 74.3,149.57 74.3,148.21 73.28,148.21 73.28,149.57
PH4 on BOTTOM (solid shape): 39.5,136.91 38.13,136.91 38.64,137.42 38.14,137.92 39.5,137.92
PH4 on BOTTOM (solid shape): 40.99,137.41 41.49,136.91 40.13,136.91 40.13,137.92 41.5,137.92
PH6 on BOTTOM (solid shape): 111.25,136.78 109.89,136.78 110.4,137.29 109.89,137.79 111.25,137.79
PH6 on BOTTOM (solid shape): 115.16,137.44 115.66,136.93 114.3,136.93 114.3,137.95 115.67,137.95
PI11 on BOTTOM (solid shape): 42.55,153.16 41.18,153.16 41.69,153.67 41.18,154.18 42.55,154.18
PI11 on BOTTOM (solid shape): 42.55,151.64 41.18,151.64 41.69,152.15 41.18,152.65 42.55,152.65
STM_RST on BOTTOM (solid shape): 38.1,30.32 37.59,29.81 37.08,30.32 37.08,31.24 38.1,31.24
U5V_ST_LINK on TOP (solid shape): 35.69,59.05 34.77,59.05 34.26,59.56 34.77,60.07 35.69,60.07
U5V_ST_LINK on TOP: 35.56,60.45 36.58,60.45 36.7,60.33 36.7,57.15 36.58,57.02 34.92,57.02 34.8,57.15 34.8,59.69
U5V_ST_LINK on BOTTOM: 36.7,59.18 36.58,59.05 35.56,59.05 35.31,59.31 35.31,61.34 35.43,61.47 36.58,61.47 36.7,61.34
ULPI_D1 on BOTTOM (solid shape): 46.45,124.33 46.95,123.83 45.59,123.83 45.59,124.84 46.96,124.84
ULPI_D2 on BOTTOM (solid shape): 46.45,141.22 46.95,140.72 45.59,140.72 45.59,141.73 46.96,141.73
ULPI_D5 on BOTTOM (solid shape): 40.99,128.9 41.49,128.4 40.13,128.4 40.13,129.41 41.5,129.41
ULPI_D7 on BOTTOM (solid shape): 48.13,153.42 46.77,153.42 47.28,153.93 46.77,154.43 48.13,154.43
VUSB_ST_LINK on TOP (solid shape): 34,59.57 34.51,59.05 33.15,59.05 33.15,60.07 34.51,60.07
VUSB_ST_LINK on L4_VCC (solid shape): 29.34,56.87 29.34,52.6 29.21,52.48 28.35,52.48 28.22,52.6 28.22,56.87 28.47,57.12 29.08,57.12
VUSB_ST_LINK on TOP: 35.05,52.96 35.46,52.55 35.46,48.08 35.33,47.96 34.19,47.96 33.25,48.9 28.83,48.9 28.19,49.53 28.19,60.07 28.7,60.58 33.66,60.58 33.78,60.45 33.78,59.18 33.66,59.05 30.35,59.05 29.97,58.67 29.97,53.59 30.61,52.96
VUSB_ST_LINK on TOP: 27.18,77.98 27.56,77.6 27.56,75.82 27.43,75.69 25.78,75.69 25.53,75.95 25.53,77.72 25.78,77.98
VUSB_ST_LINK on BOTTOM: 17.14,21.26 16.97,21.44 16.97,22.78 17.12,22.94 19.66,22.94 19.84,22.76 19.84,21.36 19.74,21.26
VUSB_ST_LINK on L3_SIG: 28.45,56.9 29.08,56.9 29.34,56.64 29.34,52.58 29.08,52.32 28.45,52.32 28.32,52.45 28.32,56.77
VUSB_ST_LINK on L3_SIG: 19.38,21.36 19.2,21.18 17.2,21.18 16.99,21.39 16.99,22.89 17.17,23.06 19.2,23.06 19.38,22.89
VUSB_ST_LINK on L3_SIG: 26.54,77.98 26.8,77.72 26.8,75.44 25.78,75.44 25.53,75.69 25.53,77.85 25.65,77.98

Small or netless copper shapes (teardrops, artwork), in the pictures only: 8 on TOP

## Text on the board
Ref Des/Silkscreen Bottom: STLINK | MFX | Rev.C | B | C | MB1165
Ref Des/Silkscreen Top: STlk | OTG_FS1 | power source | ST-LINK/V2-1 | OTG_FS2 | FS1 | FS2 | D5V | PSU | HS | Coupon | USART1 | PSU DC5V | OVER CURRENT | IrDA_RX | +5V | COM | Potentiometer | AIN | RS232_RX | BL_RST | ADC channel | STLINK | PA4 | RF E2P | +3V3 | PWR_EXT | PC0 | RESET# | GND | PA4/PC0 | PH0 | PF6 | PF10 | PA2 | PA0 | PF8 | PC2 | PC4 | PC3 | PB2 | PJ3 | PB10 | PB14 | PH6 | PB12 | PB13 | PJ9 | PG7 | PG6 | PJ7 | PJ10 | PJ8 | SW1 SW2 | 3V3 | VBAT | 0 | 1 | MFX | PH3 | PF13 | PF12 | PG1 | PE7 | PE10 | PE12 | PE15 | PE13 | PD11 | PD12 | PG5 | PH11 | PD13 | PG2 | PD8 | PD9 | PD14 | X | 0 <--> 1 | User Flash | Sys mem | SRAM | PI11 | PB5 | PH1 | PF7 | PF9 | PA1 | PC1 | PA3 | PA6 | PA7 | PA5 | PB1 | PH4 | PI14 | PJ4 | PB11 | PB15 | PH7 | PJ5 | PJ6 | PC5 | PB0 | PJ0 | PJ2 | PJ1 | 5V | BOOT | TX | RX | VDD_MCU | PH5 | PF14 | PG0 | PF11 | PE9 | PE8 | PE11 | PF15 | PE14 | PH8 | PH10 | PH9 | PG4 | PH12 | PG3 | PD10 | PD15 | PG8 | VDDA | VREF+ | Motor Control | CON | USART1_RX | USART1_TX | NOR_WP | DATA | NWAIT | PF5 | PF4 | PF3 | PE6 | PE4 | PE3 | PI5 | PI4 | PG15 | PI10 | PE1 | PE0 | PG9 | PD0 | PI2 | PI1 | PI0 | PH13 | TDO | BL_BOOT0 | CLK | I2S | PC15 | PI15 | PI12 | PI8 | PK6 | PK4 | PG12 | PG10 | PB7 | PD3 | PG13 | PJ12 | PG14 | PB8 | PG11 | PJ11 | PK0 | PA11 | PA9 | PB3 | PD6 | PC8 | PC11 | PC10 | PD2 | PH15 | PH14 | PH2 | PE5 | PF2 | PF1 | PF0 | PE2 | PI7 | PI9 | PI6 | PD7 | PD5 | PD4 | PD1 | PI3 | TRACE | PI13 | PC14 | PC13 | PK7 | PK5 | PB9 | PK3 | PB6 | PJ14 | PJ15 | PB4 | PJ13 | PC12 | PA15 | PK1 | PA14 | PK2 | PA13 | PA12 | PA10 | PC9 | PA8 | V_FS1 | PC7 | PC6 | +2V8 | IrDA | CAN terminal | +1V8 | 25MHz | Ethernet | ETH_CLK | Camera | CAN | MCO | Crystal | JTAG | uSD | OTG | -HS | MICBIAS | Audio | Audio_out2 | CAN_RX | CAN_RS | Audio_out1 | S | C | Reset | Wakeup | Joystick | MB1165 Rev.C | Tamper | STM32469I-EVAL
User.23: 1 | 3 | 5.1 | 4.1 | 6.1 | 10.9 | 8.9 | 9.9 | N/A | 90 OHM | 100 OHM | +/-10%
User.32: CN8 | CN1 | B1 | U4 | B2 | CN16 | CN3 | CN10 | CN4 | CN14_1 | U21 | CN5 | CN11 | RV2 | U10 | U27 | U7 | CN12 | U5 | CN14 | CN9 | CN13 | CN7 | CN23 | 1 | 845.00 | 545.00 | ST-Link | MB1063 | 0.00 | MB1043 | Designator5 | 400.00 | SDRAM | Speaker connector | Designator6 | Ethernet | Memory connector | Memory Connector | 118.36427 (mm)
User.38: 59 | 60 | 50 | 40 | 30 | 20 | 10 | 2 | 1 | 6 | 25
User.43: FIGURE | SIZE | 6.0 | 8.0 | 10.0 | 12.0 | 30.0 | 38.0 | 40.0 | 48.0 | 53.0 | 64.0 | 95.0 | 126.0 | 177.0 | 28.0 | 33.46 | 39.0 | 47.0 | 58.0 | 67.0 | 79.0 | 125.0 | 138.0 | 33.0x30.0 | 59.0x33.0 | 126.0x40.0 | 140.0x50.0 | TOLERANCE | +3.0/-3.0 | +2.0/-2.0 | +5.0/-5.0 | DRILL CHART: TOP to BOTTOM | ALL UNITS ARE IN MILS | PLATED | NON-PLATED | ROTATION | - | 0.000 | 90.000 | QTY | 24 | 293 | 727 | 607 | 9 | 18 | 178 | 6 | 4 | 2 | 3 | 1 | 11 | 1933 | TOTAL HOLES:
